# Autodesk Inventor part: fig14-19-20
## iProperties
Created: 2005-03
Part Number: fig14-19-20
Document SubType Name: Sheet Metal
Designer: CADCIM
Manufacturer: Standard
Standards Organization: Custom
Author: CADCIM
